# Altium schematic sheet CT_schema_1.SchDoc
size 371 x 258 mm
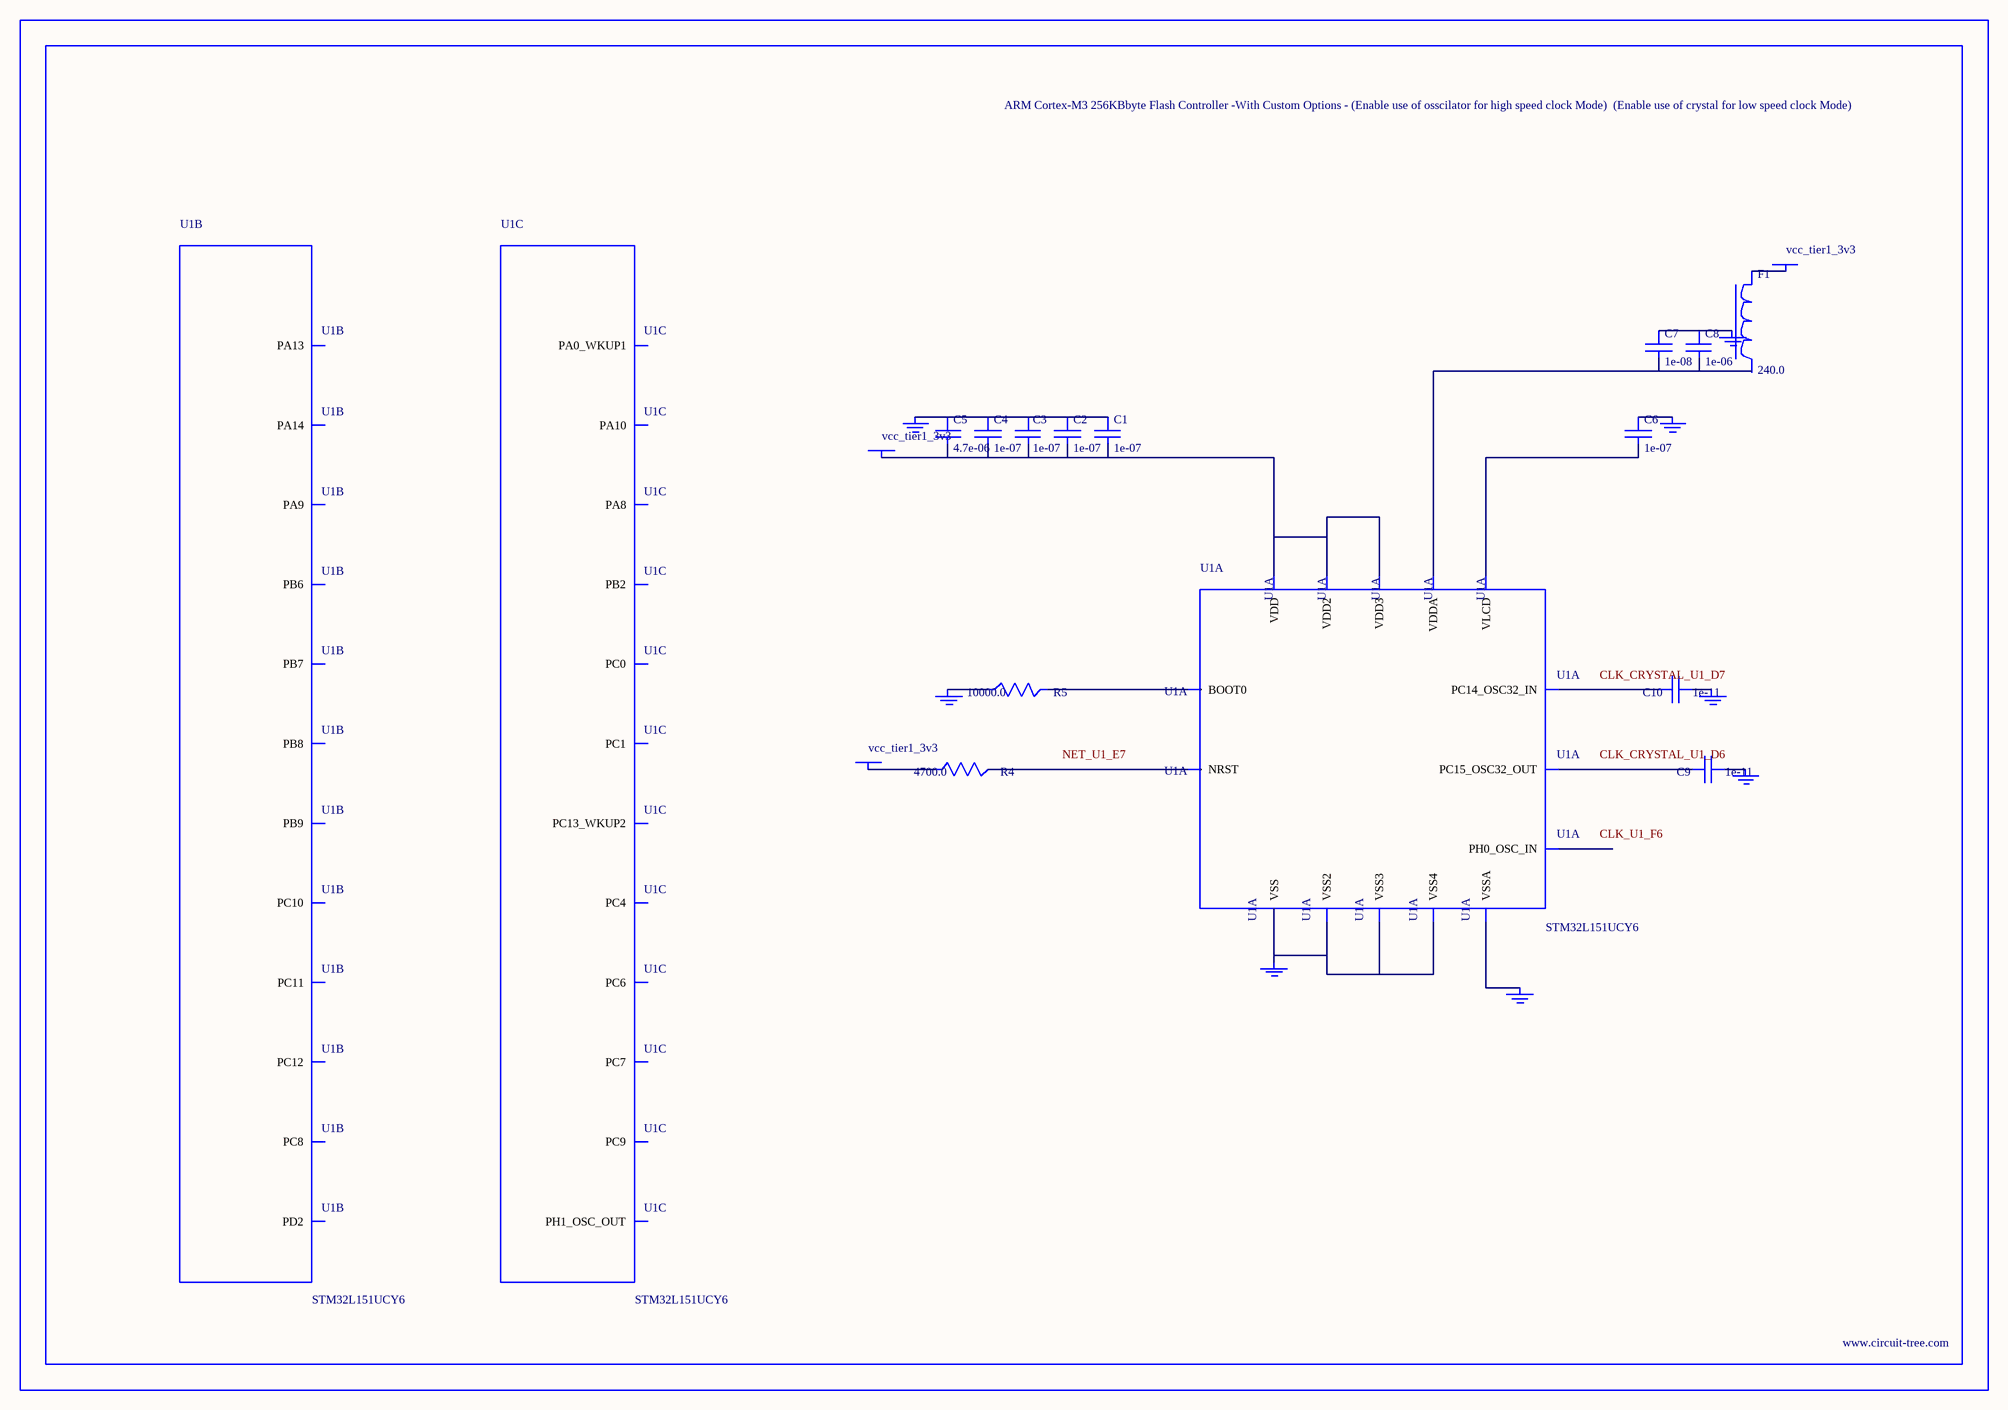
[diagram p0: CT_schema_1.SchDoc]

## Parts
BORDER0  (no value)
C1  1e-07  [C0603]
C2  1e-07  [C0603]
C3  1e-07  [C0603]
C4  1e-07  [C0603]
C5  4.7e-06  [C0603]
C6  1e-07  [C0603]
C7  1e-08  [C0603]
C8  1e-06  [C0603]
C9  1e-11  [C0402]
C10  1e-11  [C0402]
F1  240.0  [L0603]
GND_INSTANCE_0_0  (no value)
GND_INSTANCE_0_1  (no value)
GND_INSTANCE_0_2  (no value)
GND_INSTANCE_0_3  (no value)
GND_INSTANCE_0_4  (no value)
GND_INSTANCE_0_5  (no value)
GND_INSTANCE_0_6  (no value)
GND_INSTANCE_0_7  (no value)
POWER_INSTANCE_0_0  vcc_tier1_3v3
POWER_INSTANCE_0_1  vcc_tier1_3v3
POWER_INSTANCE_0_2  vcc_tier1_3v3
R4  4700.0  [R0603]
R5  10000.0  [R0603]
U1  STM32L151UCY6  [WLCSP63]  (parts A,B,C of 7)

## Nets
NetC1_1: C1.1 C2.1 C3.1 C4.1 C5.1 GND_INSTANCE_0_1.0(GND)
NetC1_2: C1.2 C2.2 C3.2 C4.2 C5.2 POWER_INSTANCE_0_1.0(PWR) U1.B2(VDD) U1.B7(VDD2) U1.H1(VDD3)
NetC6_1: C6.1 GND_INSTANCE_0_2.0(GND)
NetC6_2: C6.2 U1.C7(VLCD)
NetC7_1: C7.1 C8.1 GND_INSTANCE_0_0.0(GND)
NetC7_2: C7.2 C8.2 U1.H7(VDDA)
NetC9_1: C9.1 GND_INSTANCE_0_4.0(GND)
NetC9_2: C9.2 U1.D6(PC15_OSC32_OUT)
NetC10_1: C10.1 GND_INSTANCE_0_5.0(GND)
NetC10_2: C10.2 U1.D7(PC14_OSC32_IN)
NetF1_1: F1.1 POWER_INSTANCE_0_0.0(PWR)
NetGND_INSTANCE_0_3_0: GND_INSTANCE_0_3.0(GND) R5.1
NetGND_INSTANCE_0_6_0: GND_INSTANCE_0_6.0(GND) U1.F5(VSSA)
NetGND_INSTANCE_0_7_0: GND_INSTANCE_0_7.0(GND) U1.A1(VSS) U1.A7(VSS2) U1.H5(VSS3) U1.J1(VSS4)
NetPOWER_INSTANCE_0_2_0: POWER_INSTANCE_0_2.0(PWR) R4.1
NetR4_2: R4.2 U1.E7(NRST)
NetR5_2: R5.2 U1.A6(BOOT0)

Not connected (* = marked no-connect by the designer): F1 2; U1 A3(PC11) A4(PD2) B3(PC10) B4(PC12) B5(PB6) B6(PB8) C1(PA9) C2(PA13) C3(PA14) C5(PB7) C6(PB9) D1(PC8) D2(PA10) D5(PC13_WKUP2) E1(PC7) E2(PC9) E3(PA8) E4(PA0_WKUP1) E5(PC1) E6(PC0) F1(PC6) F4(PC4) F6(PH0_OSC_IN) F7(PH1_OSC_OUT) G3(PB2)

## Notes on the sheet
- Labels drawn without touching a wire or pin: CLK_CRYSTAL_U1_D6, CLK_CRYSTAL_U1_D7, CLK_U1_F6, NET_U1_E7

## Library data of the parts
BORDER0 = BORDER_PAGE0
C1-C4 C6 = 06035C104K4Z2A
C5 = GRM188R6YA475KE15D
C7 = 06035C103K4Z2A
C8 = C0603C105K3RACTU
C9 C10 = C0402C100K3GACTU
F1 = Z0603C241ASMST
GND_INSTANCE_0_0-GND_INSTANCE_0_7 = GND
POWER_INSTANCE_0_0-POWER_INSTANCE_0_2 = PWR
R4 = RC0603JR-074K7L
R5 = RC0603JR-0710KL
